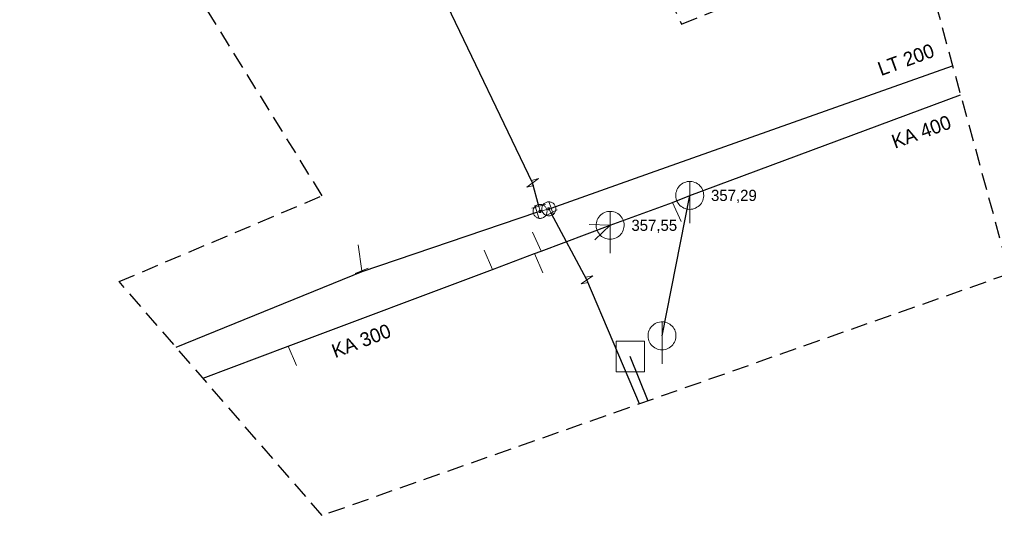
# Model space of a CAD drawing. Extents: x -688691 to -688449, y -974248 to -973966.
# Drawn here: x -688629.3 to -688559.6, y -974248 to -974212.5 of the extents above; entities that cross this region are included whole.
import ezdxf

# ---------------------------------------------------------------- set-up
doc = ezdxf.new("R2010")
doc.units = 0
doc.header["$LTSCALE"] = 0.4
doc.linetypes.add('MEDIUM_DASHED', pattern=[4.5, 3, -1.5])
for name, color, linetype, lineweight in [('1', 7, 'MEDIUM_DASHED', 25), ('11', 7, 'Continuous', 13), ('13', 7, 'Continuous', 13), ('14', 7, 'Continuous', 25), ('17', 7, 'Continuous', 25), ('22', 7, 'Continuous', 13), ('34', 7, 'Continuous', 13), ('47', 7, 'Continuous', 13)]:
    doc.layers.add(name, color=color, linetype=linetype, lineweight=lineweight)

msp = doc.modelspace()

# ---------------------------------------------------------------- linework, layer by layer
at = {"layer": '1'}
msp.add_lwpolyline([(-688492.642, -974007.422), (-688474.778, -973965.553), (-688449.099, -973975.602), (-688472.545, -974030.309), (-688492.642, -974033.659), (-688555.165, -974021.936), (-688650.066, -974071.061), (-688624.387, -974128.002), (-688613.222, -974120.745), (-688593.125, -974162.055), (-688604.29, -974165.404), (-688581.96, -974212.855), (-688565.213, -974206.156), (-688558.514, -974230.719), (-688607.64, -974248.024), (-688622.154, -974231.277), (-688607.64, -974225.136), (-688626.62, -974194.433), (-688691.376, -974059.338), (-688565.213, -973995.698), (-688544, -974002.397)], close=True, dxfattribs=at)
at = {"layer": '11'}
for p, q in [((-688581.987, -974226.982), (-688582.596, -974225.609)), ((-688588.559, -974227.204), (-688587.059, -974227.25)), ((-688588.14, -974228.291), (-688587.059, -974227.25)), ((-688592.6, -974227.739), (-688591.976, -974229.096)), ((-688596.066, -974229.03), (-688595.477, -974230.418)), ((-688591.862, -974230.649), (-688592.473, -974229.278)), ((-688609.482, -974237.289), (-688610.061, -974235.906))]:
    msp.add_line(p, q, dxfattribs=at)
at = {"layer": '13'}
msp.add_line((-688604.81, -974230.5), (-688605.076, -974228.66), dxfattribs=at)
at = {"layer": '14'}
for p, q in [((-688583.35, -974235.16), (-688581.37, -974225.109)), ((-688585.655, -974236.627), (-688584.368, -974239.826))]:
    msp.add_line(p, q, dxfattribs=at)
at = {"layer": '14', "lineweight": 13}
for p, q in [((-688591.441, -974226.072), (-688591.282, -974226.37)), ((-688604.789, -974230.552), (-688604.81, -974230.5))]:
    msp.add_line(p, q, dxfattribs=at)
at = {"layer": '14'}
for points in [[(-688587.059, -974227.25), (-688582.596, -974225.609), (-688581.37, -974225.109), (-688562.006, -974217.915)], [(-688616.155, -974238.199), (-688610.061, -974235.906), (-688595.477, -974230.418), (-688592.473, -974229.278), (-688591.976, -974229.096), (-688587.059, -974227.25)]]:
    msp.add_lwpolyline(points, dxfattribs=at)
at = {"layer": '14', "lineweight": 13}
for points in [[(-688592.289, -974226.318), (-688592.068, -974226.254), (-688592.162, -974225.892)], [(-688592.068, -974226.254), (-688591.441, -974226.072), (-688591.276, -974226.024)]]:
    msp.add_lwpolyline(points, dxfattribs=at)
at = {"layer": '17'}
for p, q in [((-688592.598, -974224.214), (-688612.61, -974182.51)), ((-688592.162, -974225.892), (-688592.598, -974224.214)), ((-688588.712, -974231.16), (-688591.282, -974226.37)), ((-688584.956, -974240.033), (-688588.712, -974231.16))]:
    msp.add_line(p, q, dxfattribs=at)
for points in [[(-688591.276, -974226.024), (-688584.18, -974223.5), (-688562.575, -974215.829)], [(-688618.075, -974235.983), (-688604.789, -974230.552), (-688592.289, -974226.318)]]:
    msp.add_lwpolyline(points, dxfattribs=at)
at = {"layer": '22'}
for p, q in [((-688581.37, -974227.109), (-688581.369, -974224.109)), ((-688587.059, -974229.25), (-688587.058, -974226.25)), ((-688583.35, -974237.16), (-688583.349, -974234.16))]:
    msp.add_line(p, q, dxfattribs=at)
for points in [[(-688580.37, -974225.109), (-688580.375, -974225), (-688580.393, -974224.892), (-688580.423, -974224.786), (-688580.463, -974224.685), (-688580.515, -974224.588), (-688580.577, -974224.498), (-688580.649, -974224.415), (-688580.729, -974224.341), (-688580.817, -974224.275), (-688580.911, -974224.22), (-688581.011, -974224.175), (-688581.116, -974224.142), (-688581.223, -974224.12), (-688581.332, -974224.11), (-688581.442, -974224.112), (-688581.55, -974224.126), (-688581.657, -974224.151), (-688581.76, -974224.188), (-688581.858, -974224.237), (-688581.95, -974224.295), (-688582.036, -974224.364), (-688582.113, -974224.441), (-688582.182, -974224.527), (-688582.241, -974224.619), (-688582.289, -974224.717), (-688582.326, -974224.82), (-688582.352, -974224.927), (-688582.366, -974225.035), (-688582.369, -974225.145), (-688582.359, -974225.254), (-688582.338, -974225.361), (-688582.304, -974225.465), (-688582.26, -974225.565), (-688582.205, -974225.66), (-688582.139, -974225.748), (-688582.065, -974225.828), (-688581.982, -974225.9), (-688581.892, -974225.962), (-688581.796, -974226.014), (-688581.694, -974226.055), (-688581.589, -974226.085), (-688581.481, -974226.103), (-688581.371, -974226.109), (-688581.262, -974226.103), (-688581.154, -974226.085), (-688581.049, -974226.056), (-688580.947, -974226.015), (-688580.85, -974225.963), (-688580.76, -974225.901), (-688580.677, -974225.83), (-688580.602, -974225.75), (-688580.537, -974225.662), (-688580.481, -974225.568), (-688580.437, -974225.468), (-688580.403, -974225.364), (-688580.381, -974225.256), (-688580.371, -974225.147)], [(-688586.059, -974227.25), (-688586.064, -974227.141), (-688586.082, -974227.033), (-688586.112, -974226.927), (-688586.152, -974226.826), (-688586.204, -974226.729), (-688586.266, -974226.639), (-688586.338, -974226.556), (-688586.418, -974226.482), (-688586.506, -974226.416), (-688586.6, -974226.361), (-688586.7, -974226.316), (-688586.805, -974226.283), (-688586.912, -974226.261), (-688587.021, -974226.251), (-688587.131, -974226.253), (-688587.239, -974226.267), (-688587.346, -974226.292), (-688587.449, -974226.329), (-688587.547, -974226.378), (-688587.639, -974226.436), (-688587.725, -974226.505), (-688587.802, -974226.582), (-688587.871, -974226.668), (-688587.93, -974226.76), (-688587.978, -974226.858), (-688588.015, -974226.961), (-688588.041, -974227.068), (-688588.055, -974227.176), (-688588.058, -974227.286), (-688588.048, -974227.395), (-688588.027, -974227.502), (-688587.993, -974227.606), (-688587.949, -974227.706), (-688587.894, -974227.801), (-688587.828, -974227.889), (-688587.754, -974227.969), (-688587.671, -974228.041), (-688587.581, -974228.103), (-688587.485, -974228.155), (-688587.383, -974228.196), (-688587.278, -974228.226), (-688587.17, -974228.244), (-688587.06, -974228.25), (-688586.951, -974228.244), (-688586.843, -974228.226), (-688586.738, -974228.197), (-688586.636, -974228.156), (-688586.539, -974228.104), (-688586.449, -974228.042), (-688586.366, -974227.971), (-688586.291, -974227.891), (-688586.226, -974227.803), (-688586.17, -974227.709), (-688586.126, -974227.609), (-688586.092, -974227.505), (-688586.07, -974227.397), (-688586.06, -974227.288)], [(-688582.35, -974235.16), (-688582.355, -974235.051), (-688582.373, -974234.943), (-688582.403, -974234.837), (-688582.443, -974234.736), (-688582.495, -974234.639), (-688582.557, -974234.549), (-688582.629, -974234.466), (-688582.709, -974234.392), (-688582.797, -974234.326), (-688582.891, -974234.271), (-688582.991, -974234.226), (-688583.096, -974234.193), (-688583.203, -974234.171), (-688583.312, -974234.161), (-688583.422, -974234.163), (-688583.53, -974234.177), (-688583.637, -974234.202), (-688583.74, -974234.239), (-688583.838, -974234.288), (-688583.93, -974234.346), (-688584.016, -974234.415), (-688584.093, -974234.492), (-688584.162, -974234.578), (-688584.221, -974234.67), (-688584.269, -974234.768), (-688584.306, -974234.871), (-688584.332, -974234.978), (-688584.346, -974235.086), (-688584.349, -974235.196), (-688584.339, -974235.305), (-688584.318, -974235.412), (-688584.284, -974235.516), (-688584.24, -974235.616), (-688584.185, -974235.711), (-688584.119, -974235.799), (-688584.045, -974235.879), (-688583.962, -974235.951), (-688583.872, -974236.013), (-688583.776, -974236.065), (-688583.674, -974236.106), (-688583.569, -974236.136), (-688583.461, -974236.154), (-688583.351, -974236.16), (-688583.242, -974236.154), (-688583.134, -974236.136), (-688583.029, -974236.107), (-688582.927, -974236.066), (-688582.83, -974236.014), (-688582.74, -974235.952), (-688582.657, -974235.881), (-688582.582, -974235.801), (-688582.517, -974235.713), (-688582.461, -974235.619), (-688582.417, -974235.519), (-688582.383, -974235.415), (-688582.361, -974235.307), (-688582.351, -974235.198)], [(-688586.635, -974235.537), (-688584.602, -974235.537), (-688584.602, -974237.73), (-688586.635, -974237.73)]]:
    msp.add_lwpolyline(points, close=True, dxfattribs=at)
at = {"layer": '34'}
for p, q in [((-688592.645, -974226.017), (-688591.677, -974225.767)), ((-688592.449, -974225.844), (-688592.129, -974226.791)), ((-688591.444, -974225.553), (-688591.108, -974226.495)), ((-688590.841, -974226.133), (-688591.723, -974226.605)), ((-688605.272, -974230.689), (-688604.346, -974230.311))]:
    msp.add_line(p, q, dxfattribs=at)
at = {"layer": '47'}
for p, q in [((-688593.006, -974224.518), (-688592.511, -974224.395)), ((-688589.134, -974231.445), (-688588.633, -974231.345))]:
    msp.add_line(p, q, dxfattribs=at)
for points in [[(-688593.006, -974224.518), (-688592.189, -974223.909), (-688592.684, -974224.032)], [(-688589.134, -974231.445), (-688588.289, -974230.874), (-688588.79, -974230.974)]]:
    msp.add_lwpolyline(points, dxfattribs=at)
for points in [[(-688591.587, -974226.115), (-688591.604, -974226.066), (-688591.626, -974226.018), (-688591.654, -974225.974), (-688591.685, -974225.932), (-688591.721, -974225.893), (-688591.761, -974225.859), (-688591.804, -974225.83), (-688591.849, -974225.804), (-688591.897, -974225.784), (-688591.947, -974225.768), (-688591.999, -974225.758), (-688592.051, -974225.754), (-688592.103, -974225.755), (-688592.155, -974225.762), (-688592.206, -974225.773), (-688592.255, -974225.79), (-688592.303, -974225.812), (-688592.348, -974225.84), (-688592.389, -974225.871), (-688592.428, -974225.907), (-688592.462, -974225.947), (-688592.492, -974225.99), (-688592.517, -974226.036), (-688592.538, -974226.083), (-688592.553, -974226.133), (-688592.563, -974226.185), (-688592.568, -974226.237), (-688592.566, -974226.289), (-688592.559, -974226.341), (-688592.548, -974226.392), (-688592.531, -974226.441), (-688592.509, -974226.489), (-688592.482, -974226.534), (-688592.45, -974226.575), (-688592.414, -974226.614), (-688592.375, -974226.648), (-688592.332, -974226.678), (-688592.286, -974226.704), (-688592.238, -974226.724), (-688592.188, -974226.739), (-688592.136, -974226.749), (-688592.085, -974226.754), (-688592.032, -974226.752), (-688591.98, -974226.745), (-688591.929, -974226.734), (-688591.88, -974226.717), (-688591.832, -974226.695), (-688591.788, -974226.668), (-688591.746, -974226.636), (-688591.707, -974226.6), (-688591.673, -974226.561), (-688591.644, -974226.518), (-688591.618, -974226.473), (-688591.598, -974226.424), (-688591.582, -974226.374), (-688591.572, -974226.322), (-688591.568, -974226.271), (-688591.569, -974226.218), (-688591.576, -974226.166)], [(-688590.96, -974225.932), (-688590.978, -974225.883), (-688591, -974225.835), (-688591.027, -974225.791), (-688591.058, -974225.749), (-688591.094, -974225.711), (-688591.134, -974225.677), (-688591.177, -974225.647), (-688591.223, -974225.622), (-688591.271, -974225.602), (-688591.321, -974225.586), (-688591.373, -974225.576), (-688591.425, -974225.572), (-688591.477, -974225.573), (-688591.529, -974225.58), (-688591.58, -974225.591), (-688591.629, -974225.609), (-688591.677, -974225.631), (-688591.722, -974225.659), (-688591.763, -974225.689), (-688591.801, -974225.725), (-688591.835, -974225.765), (-688591.866, -974225.809), (-688591.891, -974225.854), (-688591.911, -974225.902), (-688591.926, -974225.952), (-688591.936, -974226.004), (-688591.941, -974226.056), (-688591.939, -974226.108), (-688591.932, -974226.16), (-688591.921, -974226.211), (-688591.903, -974226.26), (-688591.881, -974226.308), (-688591.854, -974226.353), (-688591.823, -974226.394), (-688591.787, -974226.432), (-688591.747, -974226.467), (-688591.704, -974226.497), (-688591.659, -974226.522), (-688591.61, -974226.542), (-688591.56, -974226.557), (-688591.508, -974226.567), (-688591.457, -974226.572), (-688591.404, -974226.57), (-688591.352, -974226.563), (-688591.301, -974226.552), (-688591.252, -974226.534), (-688591.204, -974226.512), (-688591.16, -974226.486), (-688591.118, -974226.454), (-688591.08, -974226.418), (-688591.045, -974226.378), (-688591.016, -974226.336), (-688590.991, -974226.29), (-688590.971, -974226.241), (-688590.955, -974226.191), (-688590.945, -974226.139), (-688590.941, -974226.088), (-688590.942, -974226.035), (-688590.949, -974225.983)], [(-688591.989, -974226.231), (-688591.991, -974226.222), (-688591.995, -974226.215), (-688591.999, -974226.208), (-688592.005, -974226.201), (-688592.011, -974226.194), (-688592.017, -974226.189), (-688592.024, -974226.184), (-688592.032, -974226.18), (-688592.04, -974226.177), (-688592.048, -974226.174), (-688592.057, -974226.172), (-688592.065, -974226.172), (-688592.073, -974226.172), (-688592.082, -974226.172), (-688592.09, -974226.175), (-688592.099, -974226.177), (-688592.106, -974226.181), (-688592.113, -974226.185), (-688592.12, -974226.191), (-688592.127, -974226.197), (-688592.132, -974226.203), (-688592.137, -974226.21), (-688592.141, -974226.218), (-688592.145, -974226.226), (-688592.147, -974226.234), (-688592.149, -974226.243), (-688592.149, -974226.251), (-688592.149, -974226.259), (-688592.149, -974226.268), (-688592.146, -974226.276), (-688592.144, -974226.285), (-688592.14, -974226.292), (-688592.136, -974226.299), (-688592.13, -974226.306), (-688592.124, -974226.313), (-688592.119, -974226.318), (-688592.111, -974226.323), (-688592.103, -974226.327), (-688592.095, -974226.331), (-688592.087, -974226.333), (-688592.078, -974226.335), (-688592.07, -974226.335), (-688592.062, -974226.335), (-688592.053, -974226.335), (-688592.045, -974226.332), (-688592.036, -974226.33), (-688592.029, -974226.326), (-688592.022, -974226.322), (-688592.015, -974226.316), (-688592.008, -974226.31), (-688592.003, -974226.305), (-688591.998, -974226.297), (-688591.994, -974226.289), (-688591.991, -974226.281), (-688591.988, -974226.273), (-688591.986, -974226.264), (-688591.986, -974226.256), (-688591.986, -974226.248), (-688591.986, -974226.239)], [(-688591.362, -974226.049), (-688591.364, -974226.04), (-688591.368, -974226.033), (-688591.373, -974226.026), (-688591.378, -974226.019), (-688591.384, -974226.012), (-688591.39, -974226.007), (-688591.397, -974226.002), (-688591.405, -974225.998), (-688591.413, -974225.995), (-688591.421, -974225.992), (-688591.43, -974225.99), (-688591.438, -974225.99), (-688591.446, -974225.99), (-688591.455, -974225.99), (-688591.463, -974225.993), (-688591.472, -974225.995), (-688591.479, -974225.999), (-688591.486, -974226.004), (-688591.493, -974226.009), (-688591.5, -974226.015), (-688591.505, -974226.021), (-688591.51, -974226.028), (-688591.514, -974226.036), (-688591.518, -974226.044), (-688591.52, -974226.052), (-688591.522, -974226.061), (-688591.522, -974226.069), (-688591.522, -974226.077), (-688591.522, -974226.086), (-688591.519, -974226.094), (-688591.517, -974226.103), (-688591.513, -974226.11), (-688591.508, -974226.117), (-688591.503, -974226.124), (-688591.497, -974226.131), (-688591.491, -974226.136), (-688591.484, -974226.141), (-688591.476, -974226.145), (-688591.468, -974226.149), (-688591.46, -974226.151), (-688591.451, -974226.153), (-688591.443, -974226.153), (-688591.435, -974226.153), (-688591.426, -974226.153), (-688591.418, -974226.15), (-688591.409, -974226.148), (-688591.402, -974226.144), (-688591.395, -974226.139), (-688591.388, -974226.134), (-688591.381, -974226.128), (-688591.376, -974226.122), (-688591.371, -974226.115), (-688591.367, -974226.107), (-688591.364, -974226.099), (-688591.361, -974226.091), (-688591.359, -974226.082), (-688591.359, -974226.074), (-688591.359, -974226.066), (-688591.359, -974226.057)]]:
    msp.add_lwpolyline(points, close=True, dxfattribs=at)

# ---------------------------------------------------------------- texts
at = {"layer": '1'}
for s, rotation, p in [('LT 200', 20, (-688567.699, -974216.573)), ('KA 400', 20, (-688566.704, -974221.775)), ('KA 300', 21, (-688606.717, -974236.769))]:
    msp.add_text(s, height=1, rotation=rotation, dxfattribs=at).set_placement(p)
for s, p in [('357,29', (-688579.848, -974225.509)), ('357,55', (-688585.538, -974227.649))]:
    msp.add_text(s, height=0.8, dxfattribs=at).set_placement(p)

doc.saveas('drawing.dxf')
